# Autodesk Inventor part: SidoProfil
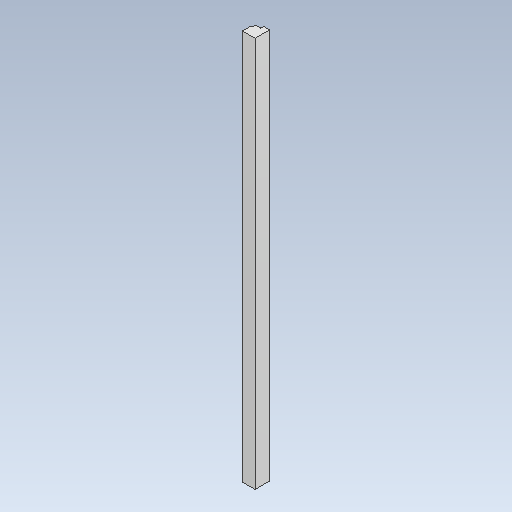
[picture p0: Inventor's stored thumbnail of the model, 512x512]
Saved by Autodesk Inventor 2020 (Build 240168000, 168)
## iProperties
Created: 2019-06
Part Number: SidoProfil
Material: Aluminum
Document SubType Name: Modeling
Designer: cl
Density: 2.7 g/cm^3
Appearance: Satin
Author: cl
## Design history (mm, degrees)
sketch "Sketch1"
  geometry: L1 (0, 0)-(87, 0); L2 (87, 0)-(87, -60); L3 (87, -60)-(77, -60); L4 (77, -60)-(77, -80); L5 (77, -80)-(40, -80); L6 (40, -80)-(40, -100); L7 (40, -100)-(0, -100); L8 (0, -100)-(0, 0)
  constraints: 16 end point, 5 perpendicular, 2 horizontal
  dimensions: "d0" = 87 distance of L1.start L1.end; "d1" = 60 distance of L1.end L2.end; "d2" = 10 distance of L2.end L3.end; "d3" = 20 distance of L3.end L4.end; "d4" = 37 distance of L4.end L5.end; "d5" = 20 distance of L5.end L6.end; "d6" = 40 distance of L6.end L7.end
extrude "Extrusion1" new body sketch "Sketch1" distance "d7" = 2690 (computed from Daghöjd); taper "d8" = 0 deg
body "Solid1"
